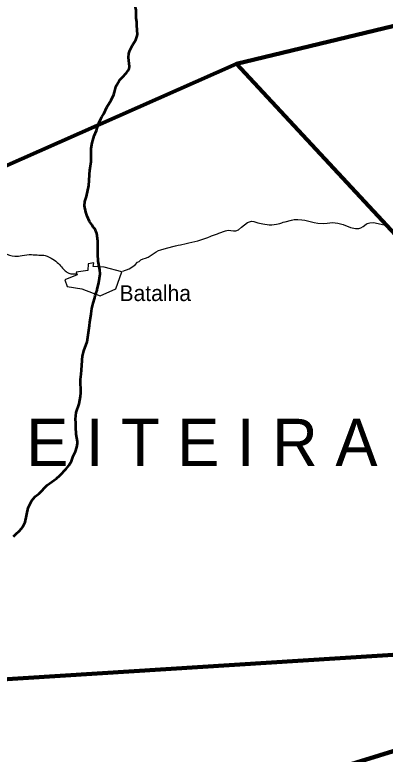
# Model space of a CAD drawing. Extents: x 553962 to 842807, y 8883888 to 9032388.
# Drawn here: x 703290 to 715039, y 8914830 to 8938264 of the extents above; entities that cross this region are included whole.
import ezdxf
from ezdxf.enums import TextEntityAlignment as Align

# ---------------------------------------------------------------- set-up
doc = ezdxf.new("R2010")
doc.units = 0
doc.header["$LTSCALE"] = 200
for name, color, linetype, lineweight in [('12', 7, 'Continuous', 25), ('21', 7, 'Continuous', 25), ('24', 7, 'Continuous', 25), ('9', 7, 'Continuous', 90)]:
    doc.layers.add(name, color=color, linetype=linetype, lineweight=lineweight)
doc.layers.add('41', color=7, linetype='Continuous')
doc.layers.add('42', color=7, linetype='Continuous')

msp = doc.modelspace()

# ---------------------------------------------------------------- linework, layer by layer
at = {"layer": '12'}
for points in [[(709408.8, 8931206.7), (709506, 8931244.1), (709530.5, 8931254.4), (709718.5, 8931325.6), (709756.5, 8931340.2), (709970.9, 8931418.8), (710057.5, 8931433), (710222.4, 8931413.2), (710303.9, 8931419.1), (710382.8, 8931452.2), (710482.4, 8931530.5), (710672.9, 8931677.7), (710731.3, 8931706.9)], [(710731.3, 8931706.9), (710792.4, 8931720.3), (710870, 8931709.1), (710995.6, 8931673.3), (711155.5, 8931637), (711358.4, 8931611), (711439, 8931609.2), (711519.6, 8931616.5), (711595.6, 8931631.9), (711691.4, 8931654.4), (711758.3, 8931674.8), (711801.8, 8931686.3), (711865.2, 8931703.9)], [(711865.2, 8931703.9), (712062.8, 8931758.7), (712149.2, 8931774.2), (712270.1, 8931781.1), (712394.1, 8931770.4), (712486.3, 8931756.9), (712570, 8931737.7), (712782.6, 8931677.3), (712904.8, 8931658.7), (713073.1, 8931649.7), (713192.9, 8931656.7), (713282.3, 8931671.3), (713370.2, 8931678.6), (713537.4, 8931664.2), (713701.3, 8931615.9), (713941.9, 8931526.7), (714100.3, 8931490.7), (714142.1, 8931488.3), (714201.7, 8931495.9), (714265.5, 8931516.4), (714337.6, 8931556.1), (714431.9, 8931628.3), (714468.7, 8931648.4), (714547.9, 8931667.9), (714667.4, 8931678.5), (715103.5, 8931588.9)], [(708723.4, 8931020.2), (708811.5, 8931041), (709092.4, 8931097.6), (709408.8, 8931206.7)], [(707006.6, 8930266.8), (707103.7, 8930343), (707184.8, 8930419.8), (707230.2, 8930449.4), (707290.2, 8930499.3), (707360.5, 8930533.4), (707440.2, 8930552.8), (707519.1, 8930582), (707648.7, 8930663), (707774.6, 8930753.3), (707847.3, 8930792.2), (707921.9, 8930818.9), (708100.7, 8930870.7), (708389.3, 8930937.4), (708468.4, 8930964.3), (708541.7, 8930977.4), (708723.4, 8931020.2)], [(706708.4, 8930134.1), (706715.6, 8930134.1), (706921.2, 8930211.8), (707006.6, 8930266.8)]]:
    msp.add_lwpolyline(points, dxfattribs=at)
msp.add_spline([(697097.5, 8934365.4), (697137.8, 8934298.3), (697070.7, 8934204.4), (696976.8, 8934097.1), (696963.4, 8933962.9), (696950, 8933681.2), (696923.2, 8933466.6), (696990.2, 8933278.7), (697097.5, 8933131.2), (697285.2, 8932889.7), (697486.4, 8932795.8), (697768, 8932648.2), (698036.2, 8932460.4), (698210.5, 8932205.5), (698344.6, 8932044.5), (698559.1, 8931829.8), (698787.1, 8931749.3), (698948, 8931628.6), (699390.5, 8931266.4), (699725.7, 8931105.4), (700114.6, 8930971.2), (700651, 8930850.5), (701147.1, 8930716.3), (701442.1, 8930609), (701723.7, 8930649.2), (702072.3, 8930823.6), (702233.2, 8930904.1), (702528.2, 8930850.5), (702957.3, 8930716.3), (703292.6, 8930609), (703520.5, 8930635.8), (703815.5, 8930662.7), (704056.9, 8930649.2), (704258, 8930635.8), (704499.4, 8930515.1), (704673.7, 8930380.9), (704807.8, 8930233.3), (704915.1, 8930126), (705008.9, 8930072.4), (705236.9, 8930058.9)], degree=3, dxfattribs=at)
at = {"layer": '21'}
msp.add_lwpolyline([(706124.6, 8930262.6), (705772.7, 8930291), (705798.2, 8930406.1), (705622.6, 8930367.7), (705604.9, 8930160.7), (705235.9, 8930107), (705266.5, 8930017.5), (704872.7, 8929859.6), (704949.4, 8929648.4), (705414.2, 8929583), (706002.8, 8929352.6), (706496.2, 8929580.5), (706680.1, 8930116.3)], close=True, dxfattribs=at)
at = {"layer": '24', "lineweight": 53}
for points in [[(706694.7, 8936277.5), (706830.5, 8936420.4), (706877.2, 8936486.3), (706914.6, 8936562.2), (706925.8, 8936622), (706895.3, 8936909.3), (706911, 8937033.7), (706943.3, 8937127.2), (707023.2, 8937296.1), (707124.8, 8937469.7), (707160.2, 8937564.5), (707176.9, 8937639.3), (707157.3, 8937927.7), (707160, 8938043.5), (707144.2, 8938159.5), (707144.9, 8938416), (707112.4, 8938537.6)], [(706455.8, 8935807.1), (706498.6, 8935977.7), (706525, 8936043.1), (706615.1, 8936193.7), (706694.7, 8936277.5)], [(706053.6, 8935025.3), (706115.4, 8935124.2), (706210, 8935340.8), (706345.4, 8935560.9), (706345.4, 8935560.9), (706430.2, 8935735.6), (706455.8, 8935807.1)], [(705957, 8934832.6), (706016.1, 8934965.2), (706053.6, 8935025.3)], [(705678, 8933377.8), (705684.3, 8933403.1), (705709.2, 8933609.6), (705711.7, 8934031.1), (705741.1, 8934209.4), (705803.6, 8934425.7), (705881, 8934596.9), (705904.4, 8934674.1)], [(705904.4, 8934674.1), (705942.9, 8934801.1), (705957, 8934832.6)], [(705923, 8930675.2), (705922.4, 8931088), (705890.3, 8931333.3), (705852.8, 8931442.3), (705831.3, 8931475.9), (705777.1, 8931528.7), (705743, 8931598.9), (705663.1, 8931713.6), (705581.9, 8931877.1), (705542.5, 8932009.4), (705503.3, 8932209.2), (705508.2, 8932351.5), (705569.4, 8932508), (705640.5, 8932849.9), (705671.7, 8933352.4), (705678, 8933377.8)], [(705981.1, 8930233.2), (705937.6, 8930459), (705923, 8930675.2)], [(705906.7, 8929556.8), (705952.7, 8929774.7), (705995, 8930056.4), (705991.2, 8930180.9), (705981.1, 8930233.2)], [(705714.4, 8928785), (705737.3, 8928951.8), (705774, 8929122.5), (705823.8, 8929288.7), (705837.1, 8929367.7), (705902.7, 8929538.2), (705906.7, 8929556.8)], [(705581.6, 8927900.5), (705661.4, 8928419), (705668.1, 8928525.9), (705714.4, 8928785)], [(705429.5, 8927325.7), (705443, 8927442.9), (705477.8, 8927613.5), (705581.6, 8927900.5)], [(703328.7, 8921805.4), (703443, 8921908.1), (703548.7, 8922036.8), (703617.1, 8922184), (703718.8, 8922634.2), (703746.2, 8922702.2), (703835.8, 8922872.4), (703941.7, 8922992.8), (704066.1, 8923087.4), (704318, 8923358.7), (704612.5, 8923568.7), (704719.2, 8923658.3), (704922.8, 8923872.7), (705008.7, 8923982.7), (705085.3, 8924116.9), (705144.1, 8924270.4), (705217.1, 8924423.9), (705261.2, 8924562.9), (705283, 8924679.2), (705282.9, 8924744.8), (705239.7, 8924977.1), (705221.2, 8925199.9), (705230.3, 8925333.3), (705211.7, 8925444.3), (705241.2, 8925661.6), (705335.2, 8925935.9), (705376.3, 8926171.8), (705383.6, 8926283.7), (705379.5, 8926700.1), (705390.8, 8926871), (705410.9, 8927000.7), (705427.2, 8927305.4), (705429.5, 8927325.7)], [(703249.3, 8921734.1), (703328.7, 8921805.4)]]:
    msp.add_lwpolyline(points, dxfattribs=at)
at = {"layer": '24'}
for points in [[(705581.6, 8927900.5), (705661.4, 8928419), (705668.1, 8928525.9), (705714.4, 8928785)], [(705429.5, 8927325.7), (705443, 8927442.9), (705477.8, 8927613.5), (705581.6, 8927900.5)], [(703328.7, 8921805.4), (703443, 8921908.1), (703548.7, 8922036.8), (703617.1, 8922184), (703718.8, 8922634.2), (703746.2, 8922702.2), (703835.8, 8922872.4), (703941.7, 8922992.8), (704066.1, 8923087.4), (704318, 8923358.7), (704612.5, 8923568.7), (704719.2, 8923658.3), (704922.8, 8923872.7), (705008.7, 8923982.7), (705085.3, 8924116.9), (705144.1, 8924270.4), (705217.1, 8924423.9), (705261.2, 8924562.9), (705283, 8924679.2), (705282.9, 8924744.8), (705239.7, 8924977.1), (705221.2, 8925199.9), (705230.3, 8925333.3), (705211.7, 8925444.3), (705241.2, 8925661.6), (705335.2, 8925935.9), (705376.3, 8926171.8), (705383.6, 8926283.7), (705379.5, 8926700.1), (705390.8, 8926871), (705410.9, 8927000.7), (705427.2, 8927305.4), (705429.5, 8927325.7)], [(703249.3, 8921734.1), (703328.7, 8921805.4)]]:
    msp.add_lwpolyline(points, dxfattribs=at)
at = {"layer": '9'}
for p, q in [((710319.1, 8936704.6), (720989.4, 8925252.2)), ((702263.2, 8917164.2), (717332.2, 8918103.3)), ((710134.6, 8913345.1), (715561.4, 8915010.8))]:
    msp.add_line(p, q, dxfattribs=at)
msp.add_lwpolyline([(696242, 8937672.8), (702061.8, 8937200.5), (702208.9, 8933124.7), (710319.1, 8936704.6), (716154, 8938115.2), (724825.2, 8936103.1), (730092.7, 8935013.9)], dxfattribs=at)

# ---------------------------------------------------------------- texts
at = {"layer": '41'}
msp.add_text('Batalha', height=500, dxfattribs=at).set_placement((706611.1, 8929191.2))
at = {"layer": '42'}
msp.add_text('B A C I A  L E I T E I R A', height=1500, dxfattribs=at).set_placement((703704.8, 8923960), align=Align.CENTER)

doc.saveas('drawing.dxf')
